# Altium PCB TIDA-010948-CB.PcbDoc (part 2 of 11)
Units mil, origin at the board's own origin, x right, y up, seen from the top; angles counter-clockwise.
Board outline 8100 x 8400 mil, 8 copper layers (L01 - TOP, L02 - GND, L03 - SIG, L04 - GND, L05 - PWR, L06 - SIG, L07 - GND, L08 - BOTTOM), stack 59.656 mil thick; 711 components, 572 nets, 2646 pads, 1325 vias.
Unrouted connection lines stored in the file: 988.
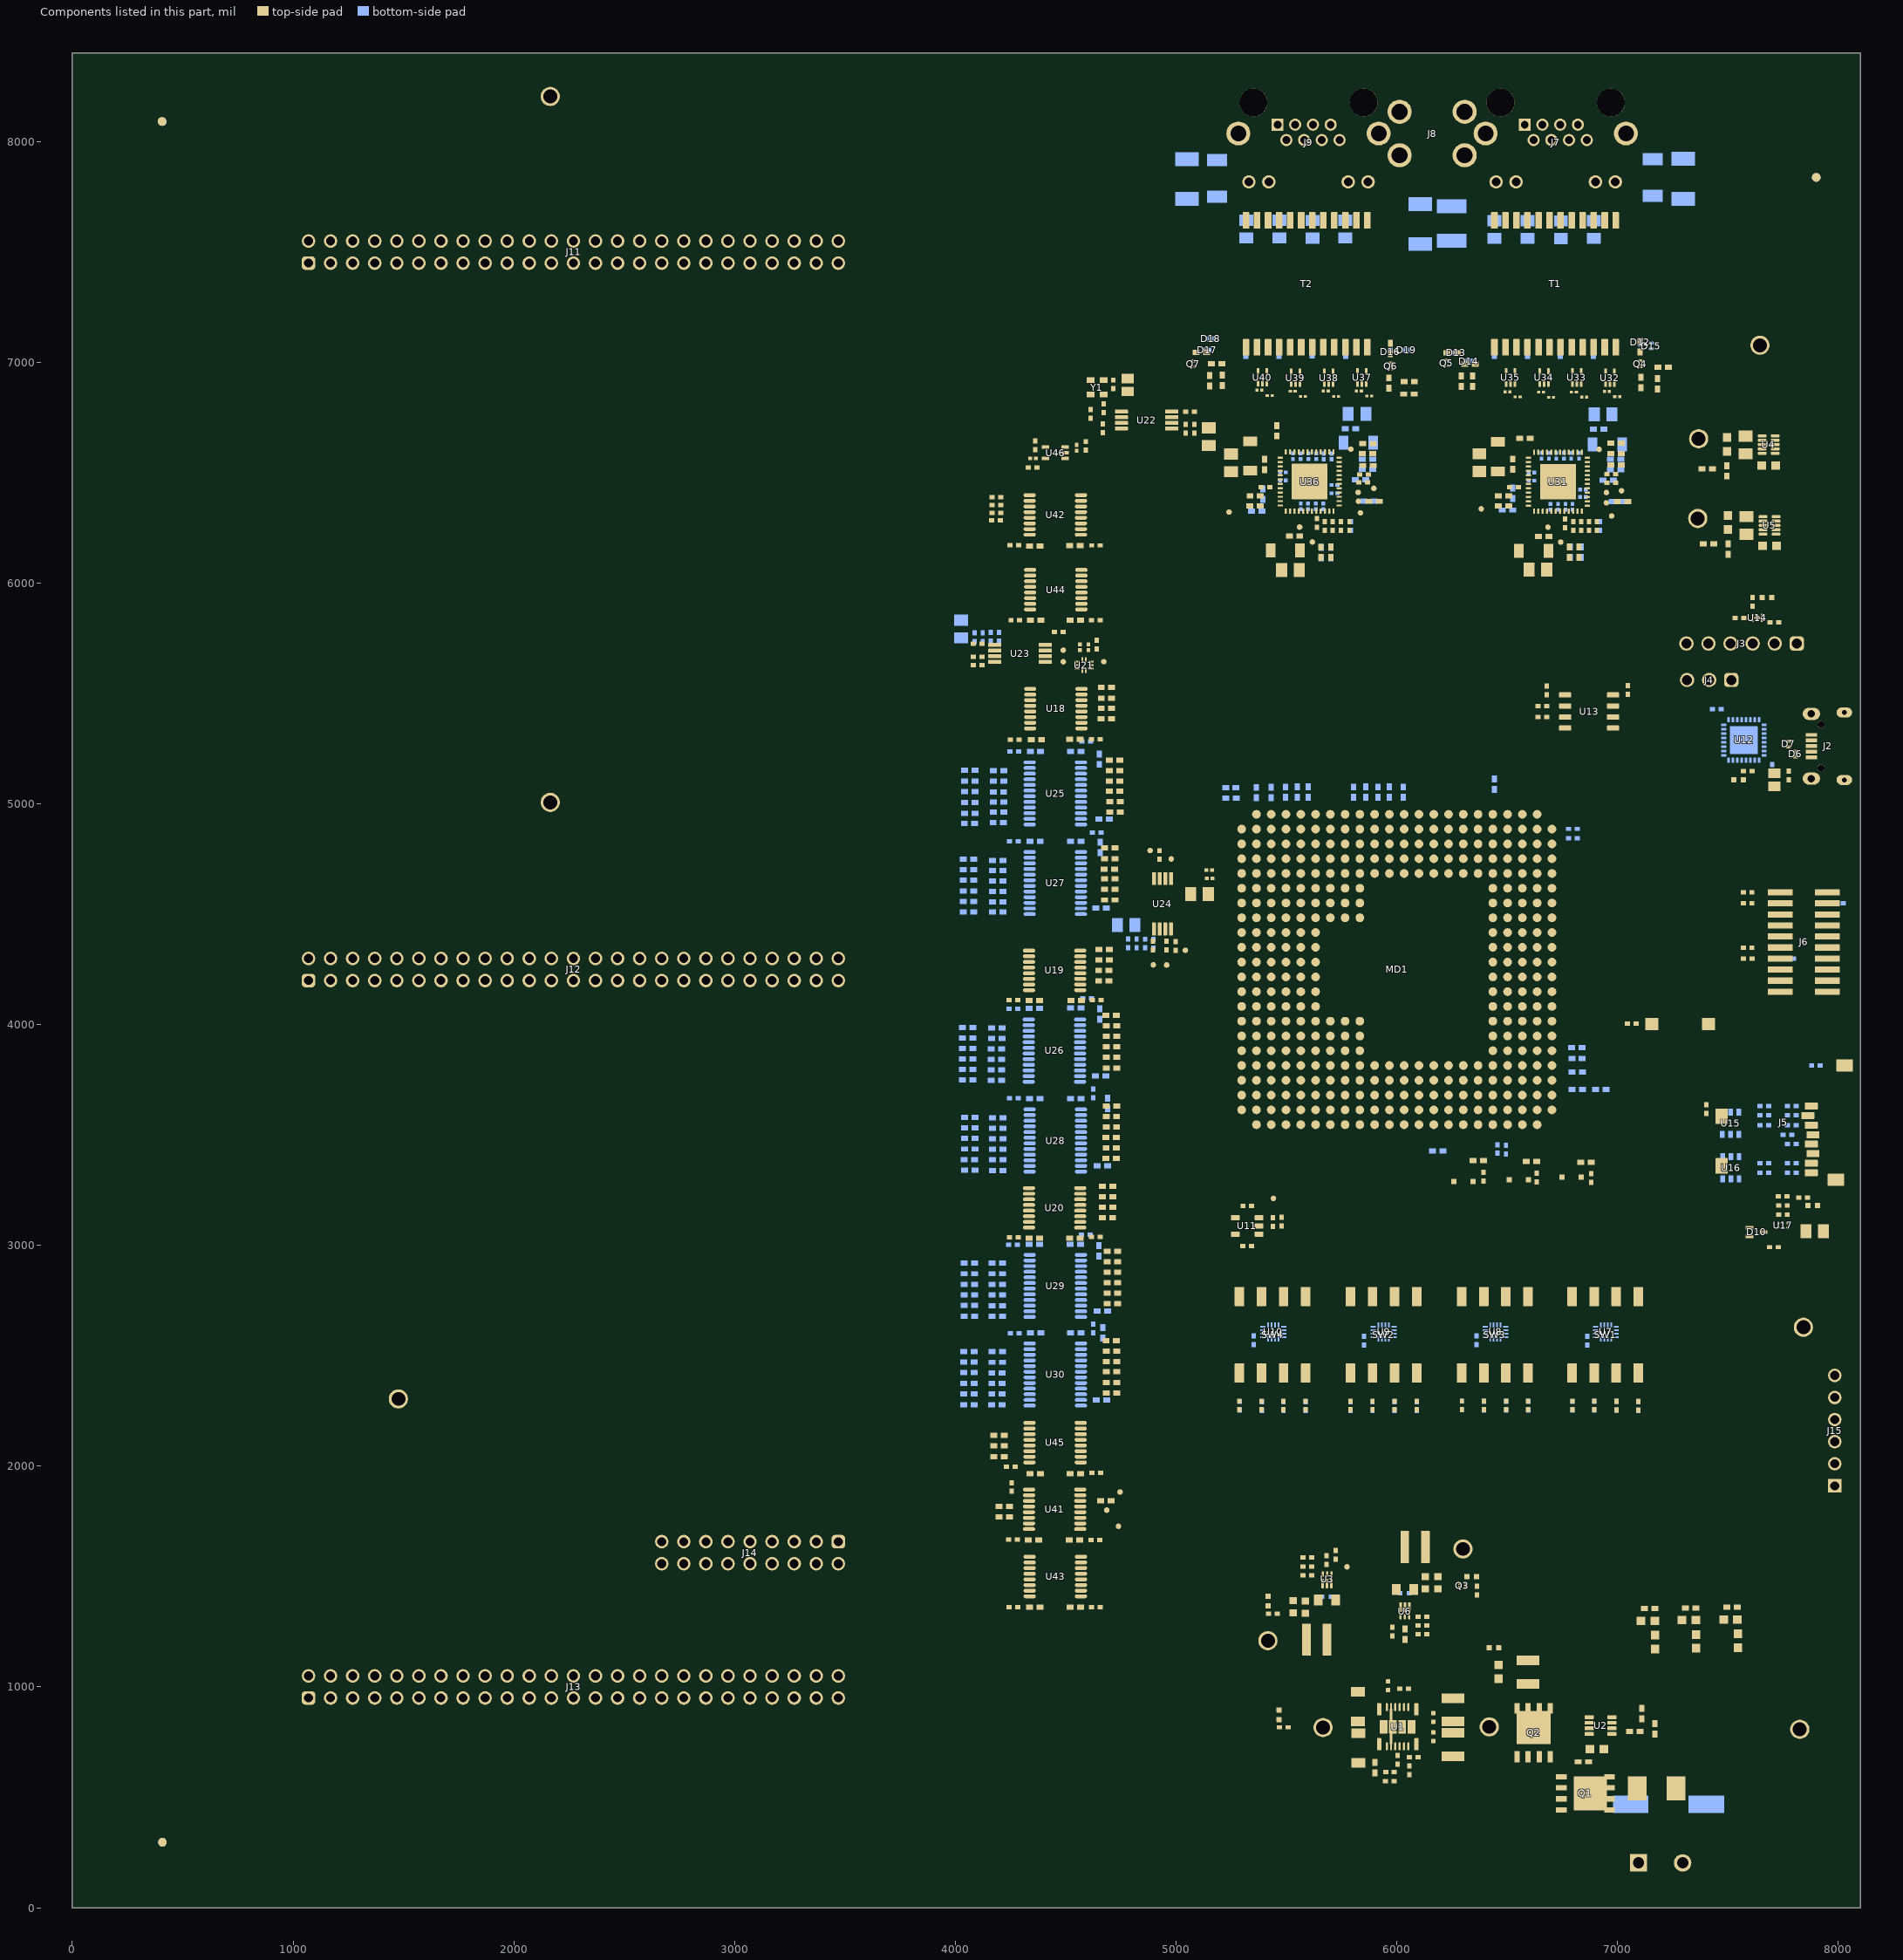
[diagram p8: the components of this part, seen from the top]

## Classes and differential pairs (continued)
net class Bootmode[0..15]: Bootmode0 Bootmode1 Bootmode2 Bootmode3 Bootmode4 Bootmode5 Bootmode6 Bootmode7 Bootmode8 Bootmode9 Bootmode10 Bootmode11 Bootmode12 Bootmode13 Bootmode14 Bootmode15
component class TIDA-010948-CB-Hardware: !PCB1 FID1 FID2 FID3 FID4 FID5 FID6 LBL1 Logo2 Logo3
component class Header: J3 J4 J6 J11 J12 J13 J14 J15
component class FiducialMark: FID1 FID2 FID3 FID4 FID5 FID6
component class Label: LBL1
differential pair ETH2_TD_D: +ETH2_TD_D_P -ETH2_TD_D_N
differential pair ETH2_TD_C: +ETH2_TD_C_P -ETH2_TD_C_N
differential pair ETH2_TD_B: +ETH2_TD_B_P -ETH2_TD_B_N
differential pair ETH2_TD_A: +ETH2_TD_A_P -ETH2_TD_A_N
differential pair ETH1_TD_D: +ETH1_TD_D_P -ETH1_TD_D_N
differential pair ETH1_TD_C: +ETH1_TD_C_P -ETH1_TD_C_N
differential pair ETH1_TD_B: +ETH1_TD_B_P -ETH1_TD_B_N
differential pair ETH1_TD_A: +ETH1_TD_A_P -ETH1_TD_A_N
differential pair E2_TD_D: +E2_TD_D_P -E2_TD_D_N
differential pair E2_TD_C: +E2_TD_C_P -E2_TD_C_N
differential pair E2_TD_B: +E2_TD_B_P -E2_TD_B_N
differential pair E2_TD_A: +E2_TD_A_P -E2_TD_A_N
differential pair E1_TD_D: +E1_TD_D_P -E1_TD_D_N
differential pair E1_TD_C: +E1_TD_C_P -E1_TD_C_N
differential pair E1_TD_B: +E1_TD_B_P -E1_TD_B_N
differential pair E1_TD_A: +E1_TD_A_P -E1_TD_A_N
differential pair FTDI_USB_D: +FTDI_USB_D_P -FTDI_USB_D_N

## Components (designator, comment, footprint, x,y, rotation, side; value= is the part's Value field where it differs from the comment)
C1 "GRM32ER71H106KA12L" 1210_270L 6255,896 r90 top locked value=10uF
C2 "GRM32ER71H106KA12L" 1210_270L 6255,739 r270 top locked value=10uF
C3 "EEE-FK1H221P" SM_RADIAL_G 7230.83,467.83 r0 bottom value=220uF
C4 "885012205086" FP-885012205086_0402-MFG 6165,774 r270 top locked value=100nF
C5 "885012205086" FP-885012205086_0402-MFG 6165,862 r90 top locked value=100nF
C6 "C3216X5R1E476M160AC" 1206_190 5825,723 r90 top locked value=47uF
C7 "C3216X5R1E476M160AC" 1206_190 5824.5,911 r270 top locked value=47uF
C8 "885012205086" FP-885012205086_0402-MFG 5961,1005 r270 top locked value=100nF
C9 "CGA2B2NP01H220J050BA" 0402L 5969,615 r0 top locked value=22pF
C10 "GRM32ER71H106KA12L" 1210_270L 6595,1067 r270 top locked value=10uF
C11 "GCM188R71H104KA57D" 0603 6906,719 r180 top locked value=0.1uF
C12 "885012205086" FP-885012205086_0402-MFG 5682,1409 r0 bottom value=100nF
C13 "C2012JB1V106K125AC" 0805_HV1 5684,1393 r180 top locked value=10uF
C14 "GRM1555C1H121JA01D" 0402L 5595,1586 r0 top value=120pF
C15 "GRM188Z71A106MA73D" 0603 7684.6,6532.26 r180 top locked value=10uF
C16 "GRM1885C1H121JA01D" 0603 7496.6,6627.26 r270 top locked value=120pF
C17 "GRM187R61A226ME15D" 0603L 5586,1362 r90 top locked value=22uF
C18 "GRM187R61A226ME15D" 0603L 5530.5,1362.5 r90 top locked value=22uF
C19 "GRM21BR61E226ME44L" 0805_HV 7580.6,6625.26 r270 top locked value=22uF
C20 "885012205086" FP-885012205086_0402-MFG 6036,1425 r180 bottom value=100nF
C21 "C2012JB1V106K125AC" 0805_HV1 6037,1441 r0 top locked value=10uF
C22 "GRM188Z71A106MA73D" 0603 7688.61,6169.05 r180 top locked value=10uF
C23 "GRM1885C1H131JA01D" 0603 7499.61,6274.05 r270 top locked value=130pF
C24 "GRM21BR61E226ME44L" 0805_HV 7584.61,6261.05 r270 top locked value=22uF
C25 "GRM1555C1H121JA01D" 0402L 6116.5,1238.5 r180 top value=120pF
C26 "GRM187R61A226ME15D" 0603L 6129,1472 r270 top locked value=22uF
C27 "GRM187R61A226ME15D" 0603L 6186,1471.5 r270 top value=22uF
C28 "885012105016" 0402L 5322,2996 r0 top value=0.1uF
C29 "GRM155R61E105MA12D" 0402L 5438,3106 r90 top value=1uF
C30 "885012105016" 0402L 6862,2568 r270 bottom value=0.1uF
C31 "885012105016" 0402L 6362,2571 r270 bottom value=0.1uF
C32 "885012105016" 0402L 5852,2568 r270 bottom value=0.1uF
C33 "885012105016" 0402L 5352,2570 r270 bottom value=0.1uF
C34 "885012105016" 0402L 7047,5516 r90 top value=0.1uF
C35 "885012105016" 0402L 6680,5514 r90 top value=0.1uF
C36 "885012105016" 0402L 7449,5429 r180 bottom value=0.1uF
C37 "885012105016" 0402L 7776,5128 r270 top value=0.1uF
C38 "885012207026" 0805L 7710,5108 r270 top value=10uF
C39 "GRM155R61E105MA12D" 0402L 7553,5842 r180 top value=1uF
C40 "GRM155R61E105MA12D" 0402L 7711,5822 r0 top value=1uF
C41 "GCM155R71C224KE02D" 0402 6857,3377 r0 top value=0.22uF
C42 "GCM155R71C224KE02D" 0402 6610,3381 r0 top value=0.22uF
C43 "GCM155R71C224KE02D" 0402 6368.5,3385 r0 top value=0.22uF
C44 "885012105012" 0402L 7749,3140 r180 top value=1uF
C45 "885012105016" 0402L 7770,3501 r180 bottom value=0.1uF
C46 "885012207026" 0805_HV 7893,3064 r0 top value=10uF
C47 "GRM155R71A104KA01D" 0402 4542.5,5291.5 r0 top value=0.1uF
C48 "GRM155R71A104KA01D" 0402 4367,5290 r0 top value=0.1uF
C49 "GRM155R71A104KA01D" 0402 4547.1,4109.65 r0 top value=0.1uF
C50 "GRM155R71A104KA01D" 0402 4357.5,4109 r0 top value=0.1uF
C51 "GRM155R71A104KA01D" 0402 4541.45,3033 r0 top value=0.1uF
C52 "GRM155R71A104KA01D" 0402 4358.5,3032.5 r0 top value=0.1uF
C53 "885012105012" 0402L 5083,6698.5 r270 top locked value=1uF
C54 "885012105016" 0402L 5043,6699 r270 top value=0.1uF
C55 "GRM033Z71C104KE14D" 0201 4564.5,5709 r90 top value=0.1uF
C56 "GRM033Z71C104KE14D" 0201 4603,5709 r270 top value=0.1uF
C57 "885012105016" 0402L 4715.5,6899.5 r270 top locked value=0.1uF
C58 "885012207092" 0805L 4780.05,6897.37 r270 top locked value=0.01uF
C59 "885012105012" 0402L 4198,5756.5 r90 bottom value=1uF
C60 "885012105016" 0402L 4086.5,5755.5 r90 bottom value=0.1uF
C61 "885012105016" 0402L 4123.93,5755.04 r90 bottom value=0.1uF
C62 "885012105016" 0402L 4159.77,5756.15 r90 bottom value=0.1uF
C63 "885012105016" 0402L 4897.69,4366.88 r270 bottom value=0.1uF
C64 "885012105012" 0402L 4782.27,4367.34 r270 bottom value=1uF
C65 "885012105016" 0402L 4821.26,4367.34 r270 bottom value=0.1uF
C66 "885012105012" 0402L 4859.62,4367.03 r270 bottom value=1uF
C67 "0402YC101KAT2A" 0402 4064.58,4911.19 r180 bottom value=100pF
C68 "0402YC101KAT2A" 0402 4064.89,4957.08 r180 bottom value=100pF
C69 "0402YC101KAT2A" 0402 4065.04,5006.33 r180 bottom value=100pF
C70 "0402YC101KAT2A" 0402 4065.5,5054.5 r180 bottom value=100pF
C71 "0402YC101KAT2A" 0402 4064.99,5102.82 r180 bottom value=100pF
C72 "0402YC101KAT2A" 0402 4064.99,5151.32 r180 bottom value=100pF
C73 "0402YC101KAT2A" 0402 4056,3749.5 r180 bottom value=100pF
C74 "0402YC101KAT2A" 0402 4056,3797.5 r180 bottom value=100pF
C75 "0402YC101KAT2A" 0402 4056,3845 r180 bottom value=100pF
C76 "0402YC101KAT2A" 0402 4056.31,3892.63 r180 bottom value=100pF
C77 "0402YC101KAT2A" 0402 4055.97,3939.21 r180 bottom value=100pF
C78 "0402YC101KAT2A" 0402 4056.23,3986.96 r180 bottom value=100pF
C79 "GRM155R71A104KA01D" 0402 4546.5,5238 r0 bottom value=0.1uF
C80 "GRM155R71A104KA01D" 0402 4546.5,4075 r0 bottom value=0.1uF
C81 "0402YC101KAT2A" 0402 4060.5,4510 r180 bottom value=100pF
C82 "0402YC101KAT2A" 0402 4060,4557 r180 bottom value=100pF
C83 "0402YC101KAT2A" 0402 4059.5,4605 r180 bottom value=100pF
C84 "0402YC101KAT2A" 0402 4059.5,4653.5 r180 bottom value=100pF
C85 "0402YC101KAT2A" 0402 4059.5,4701 r180 bottom value=100pF
C86 "0402YC101KAT2A" 0402 4059.5,4748.5 r180 bottom value=100pF
C87 "0402YC101KAT2A" 0402 4065,3340.5 r180 bottom value=100pF
C88 "0402YC101KAT2A" 0402 4064.5,3388.5 r180 bottom value=100pF
C89 "0402YC101KAT2A" 0402 4065,3436.5 r180 bottom value=100pF
C90 "0402YC101KAT2A" 0402 4065,3484 r180 bottom value=100pF
C91 "0402YC101KAT2A" 0402 4065,3531.5 r180 bottom value=100pF
C92 "0402YC101KAT2A" 0402 4065.29,3579.09 r180 bottom value=100pF
C93 "GRM155R71A104KA01D" 0402 4546.15,4830.19 r0 bottom value=0.1uF
C94 "GRM155R71A104KA01D" 0402 4545,3665.5 r0 bottom value=0.1uF
C95 "0402YC101KAT2A" 0402 4064.5,2679.5 r180 bottom value=100pF
C96 "0402YC101KAT2A" 0402 4064.5,2727.5 r180 bottom value=100pF
C97 "0402YC101KAT2A" 0402 4064,2776 r180 bottom value=100pF
C98 "0402YC101KAT2A" 0402 4064,2824 r180 bottom value=100pF
C99 "0402YC101KAT2A" 0402 4064,2871.5 r180 bottom value=100pF
C100 "0402YC101KAT2A" 0402 4064,2919.5 r180 bottom value=100pF
C101 "GRM155R71A104KA01D" 0402 4543.68,3005.21 r0 bottom value=0.1uF
C102 "0402YC101KAT2A" 0402 4061.16,2278.07 r180 bottom value=100pF
C103 "0402YC101KAT2A" 0402 4061.39,2326.39 r180 bottom value=100pF
C104 "0402YC101KAT2A" 0402 4061.18,2374.62 r180 bottom value=100pF
C105 "0402YC101KAT2A" 0402 4061.32,2423.65 r180 bottom value=100pF
C106 "0402YC101KAT2A" 0402 4061.5,2471.1 r180 bottom value=100pF
C107 "0402YC101KAT2A" 0402 4061.5,2518.5 r180 bottom value=100pF
C108 "GRM155R71A104KA01D" 0402 4546.08,2603.11 r0 bottom value=0.1uF
C109 "C3216X7R1V106M160AC" 1206_190 6457.5,6573 r90 top locked value=10uF
C110 "GRM033C71C104KE14D" 0201_033 6609.5,6500.5 r0 bottom value=0.1uF
C111 "GRM033C71C104KE14D" 0201_033 6730,6345 r90 bottom value=0.1uF
C112 "GRM155R71A104KA01D" 0402 4363,5237 r0 bottom value=0.1uF
C113 "C3216X7R1V106M160AC" 1206_190 6953.89,6628.35 r0 bottom value=10uF
C114 "GRM033C71C104KE14D" 0201_033 6790,6576.52 r270 bottom value=0.1uF
C115 "GRM033C71C104KE14D" 0201_033 6689.61,6576.62 r270 bottom value=0.1uF
C116 "C3216X7R1V106M160AC" 1206_190 6619.5,6146 r180 top locked value=10uF
C117 "GRM033C71C104KE14D" 0201_033 6764,6345 r90 bottom value=0.1uF
C118 "GRM033C71C104KE14D" 0201_033 6722.5,6577 r270 bottom value=0.1uF
C119 "GRM033C71C104KE14D" 0201_033 6843,6389.5 r180 bottom value=0.1uF
C120 "GRM155R71A104KA01D" 0402 4358,4073 r0 bottom value=0.1uF
C121 "885012205031" 0402 6525.5,6538 r90 top locked value=0.01uF
C122 "885012205031" 0402 6914.79,6696.09 r0 bottom value=0.01uF
C123 "885012205031" 0402 6666,6211.5 r180 top locked value=0.01uF
C124 "GRM033R61A105ME15D" 0201 6609.5,6463.5 r0 bottom value=1uF
C125 "GRM033R61A105ME15D" 0201 6696,6345 r90 bottom value=1uF
C126 "GRM155R71A104KA01D" 0402 4361.05,4829.5 r0 bottom value=0.1uF
C127 "GRM033R61A105ME15D" 0201 6824.76,6576.62 r270 bottom value=1uF
C128 "GRM033R61A105ME15D" 0201 6655.3,6576.75 r270 bottom value=1uF
C129 "GRM033R61A105ME15D" 0201 6796,6345 r90 bottom value=1uF
C130 "GRM033R61A105ME15D" 0201 6757.5,6577 r270 bottom value=1uF
C131 "GRM033R61A105ME15D" 0201 6843,6423.5 r180 bottom value=1uF
C132 "GRM155R71A104KA01D" 0402 4360.52,3665.11 r0 bottom value=0.1uF
C133 "GRM155R71C104KA88D" 0402 6441.5,7054.5 r270 bottom value=0.1uF
C134 "GRM155R71C104KA88D" 0402 6592,7054 r270 bottom value=0.1uF
C135 "C1005X7R1C103K050BA" 0402 6923.5,3706.5 r0 bottom value=0.01uF
C136 "885012105010" 0402 6331,6991.5 r0 top value=0.1uF
C137 "GRM155R71C104KA88D" 0402 6741,7055 r270 bottom value=0.1uF
C138 "CGA2B2NP01H220J050BA" 0402L 6530.5,6433.5 r180 top locked value=22pF
C139 "885012105010" 0402 7207,6977.5 r180 top value=0.1uF
C140 "GRM155R71C104KA88D" 0402 6891.5,7053.5 r270 bottom value=0.1uF
C141 "GR442QR73D102KW01L" 1808 7159,7837 r90 bottom value=1000pF
C142 "GRM0335C1H4R7CA01D" 0201L 6998.5,6844 r180 top value=4.7pF
C143 "GRM0335C1H4R7CA01D" 0201L 6952,6868 r0 top value=4.7pF
C144 "GRM0335C1H4R7CA01D" 0201L 6849,6842 r180 top value=4.7pF
C145 "GRM0335C1H4R7CA01D" 0201L 6802.5,6865.5 r0 top value=4.7pF
C146 "GRM0335C1H4R7CA01D" 0201L 6699.5,6841.5 r180 top value=4.7pF
C147 "GRM0335C1H4R7CA01D" 0201L 6653,6865 r0 top value=4.7pF
C148 "GRM0335C1H4R7CA01D" 0201L 6547.5,6843 r180 top value=4.7pF
C149 "GRM0335C1H4R7CA01D" 0201L 6501,6866 r0 top value=4.7pF
C150 "1812SC103KAT1A" 1812 6249,7628.5 r270 bottom value=0.01uF
C151 "C3216X7R1V106M160AC" 1206_190 5335.5,6575.5 r90 top locked value=10uF
C152 "GRM033C71C104KE14D" 0201_033 5484.5,6465 r0 bottom value=0.1uF
C153 "GRM033C71C104KE14D" 0201_033 5598,6347 r90 bottom value=0.1uF
C154 "GRM155R71A104KA01D" 0402 4357.68,3005.08 r0 bottom value=0.1uF
C155 "C3216X7R1V106M160AC" 1206_190 5825.95,6635.6 r0 bottom value=10uF
C156 "GRM033C71C104KE14D" 0201_033 5704,6573.5 r270 bottom value=0.1uF
C157 "GRM033C71C104KE14D" 0201_033 5529,6574 r270 bottom value=0.1uF
C158 "C3216X7R1V106M160AC" 1206_190 5495,6147 r180 top locked value=10uF
C159 "GRM033C71C104KE14D" 0201_033 5633,6347 r90 bottom value=0.1uF
C160 "GRM033C71C104KE14D" 0201_033 5718,6407 r180 bottom value=0.1uF
C161 "GRM033C71C104KE14D" 0201_033 5635,6574 r270 bottom value=0.1uF
C162 "GRM155R71A104KA01D" 0402 4363.5,2603 r0 bottom value=0.1uF
C163 "885012205031" 0402 5401,6537.5 r90 top locked value=0.01uF
C164 "885012205031" 0402 5790.5,6699 r0 bottom value=0.01uF
C165 "885012205031" 0402 5536.5,6213.5 r180 top locked value=0.01uF
C166 "GRM033R61A105ME15D" 0201 5484.5,6501.5 r0 bottom value=1uF
C167 "GRM033R61A105ME15D" 0201 5565.5,6347 r90 bottom value=1uF
C168 "GRM033R61A105ME15D" 0201 5151.96,4662.54 r180 top value=1uF
C169 "GRM033R61A105ME15D" 0201 5669,6573.5 r270 bottom value=1uF
C170 "GRM033R61A105ME15D" 0201 5564,6574 r270 bottom value=1uF
C171 "GRM033R61A105ME15D" 0201 5666.5,6347 r90 bottom value=1uF
C172 "GRM033R61A105ME15D" 0201 5718,6444.5 r180 bottom value=1uF
C173 "GRM033R61A105ME15D" 0201 5599.5,6574 r270 bottom value=1uF
C174 "GRM033C71C104KE14D" 0201_033 5150.5,4700 r180 top value=0.1uF
C175 "GRM155R71C104KA88D" 0402 5317,7055 r270 bottom value=0.1uF
C176 "GRM155R71C104KA88D" 0402 5467,7055 r270 bottom value=0.1uF
C177 "GRM155R71A104KA01D" 0402 7144.86,1355.4 r0 top locked value=0.1uF
C178 "885012105010" 0402 5183.5,6994 r0 top locked value=0.1uF
C179 "GRM155R71C104KA88D" 0402 5617,7057 r270 bottom value=0.1uF
C180 "CGA2B2NP01H220J050BA" 0402L 5405.5,6433.5 r180 top locked value=22pF
C181 "885012105010" 0402 6056,6912.5 r180 top locked value=0.1uF
C182 "GRM155R71C104KA88D" 0402 5768,7055 r270 bottom value=0.1uF
C183 "GR442QR73D102KW01L" 1808 5186,7833 r90 bottom value=1000pF
C184 "GRM0335C1H4R7CA01D" 0201L 5875,6846.5 r180 top locked value=4.7pF
C185 "GRM0335C1H4R7CA01D" 0201L 5828.5,6870 r0 top locked value=4.7pF
C186 "GRM0335C1H4R7CA01D" 0201L 5725,6845.5 r180 top locked value=4.7pF
C187 "GRM0335C1H4R7CA01D" 0201L 5678.5,6869.5 r0 top locked value=4.7pF
C188 "GRM0335C1H4R7CA01D" 0201L 5574.5,6845 r180 top locked value=4.7pF
C189 "GRM0335C1H4R7CA01D" 0201L 5528.5,6869 r0 top locked value=4.7pF
C190 "GRM0335C1H4R7CA01D" 0201L 5424,6849 r180 top locked value=4.7pF
C191 "GRM0335C1H4R7CA01D" 0201L 5377.5,6873.5 r0 top locked value=4.7pF
C193 "GRM155R71A104KA01D" 0402 4540.5,1665.5 r0 top value=0.1uF
C194 "GRM155R71A104KA01D" 0402 4354.44,1665.64 r0 top value=0.1uF
C195 "GRM155R71A104KA01D" 0402 4542,6170 r0 top value=0.1uF
C196 "GRM155R71A104KA01D" 0402 4360,6167 r0 top value=0.1uF
C197 "GRM155R71A104KA01D" 0402 4543.5,1362 r0 top value=0.1uF
C198 "GRM155R71A104KA01D" 0402 4359.81,1361.62 r0 top value=0.1uF
C199 "GRM155R71A104KA01D" 0402 4544.5,5831.5 r0 top value=0.1uF
C200 "GRM155R71A104KA01D" 0402 4364.79,5831.71 r0 top value=0.1uF
C201 "GRM155R71A104KA01D" 0402 4543,1966 r0 top value=0.1uF
C202 "GRM155R71A104KA01D" 0402 4362.8,1966.16 r0 top value=0.1uF
C203 "GRM033Z71C104KE14D" 0201 4351.5,6564.5 r180 top value=0.1uF
C204 "GRM033Z71C104KE14D" 0201 4549.5,6613 r90 top locked value=0.1uF
C205 "GRM155R71A104KA01D" 0402 7330.5,1357 r0 top locked value=0.1uF
C206 "GRM155R71A104KA01D" 0402 7518.38,1362.05 r0 top locked value=0.1uF
D1 "150040GS73240" WL-SMCC_0402_Green 6440,1177 r0 top locked value=Green
D2 "150040GS73240" WL-SMCC_0402_Green 5466.69,874 r270 top locked value=Green
D3 "SMBJ33CA-13-F" SMB-Bi 7177,541 r180 top locked value=33V
D4 "150040GS73240" WL-SMCC_0402_Green 5417,1389 r270 top locked value=Green
D5 "150040GS73240" WL-SMCC_0402_Green 6339.5,1500 r0 top locked value=Green
D6 "ESD321DPYR" DPY0002A#1 7806,5225.5 r270 top
D7 "ESD321DPYR" DPY0002A#1 7774,5271 r90 top
D8 "150040GS73240" WL-SMCC_0402_Green 7547.61,5109.2 r0 top value=Green
D9 "150040GS73240" WL-SMCC_0402_Green 7677,5935 r180 top value=Green
D10 "BAT54AT-7-F" SOT-523 7630,3061 r0 top value=30V
D11 "150040GS73240" WL-SMCC_0402_Green 7884.48,3180.4 r180 top value=Green
D12 "TPD1E1B04DPYR" DPY0002A#2 7102.5,7090.5 r90 bottom
D13 "TPD1E1B04DPYR" DPY0002A#2 6269,7043 r0 bottom
D14 "TPD1E1B04DPYR" DPY0002A#2 6327,7005 r0 bottom
D15 "TPD1E1B04DPYR" DPY0002A#2 7153,7073.7 r90 bottom
D16 "TPD1E1B04DPYR" DPY0002A#2 5970.5,7047 r90 bottom
D17 "TPD1E1B04DPYR" DPY0002A#2 5140.5,7055.5 r0 bottom
D18 "TPD1E1B04DPYR" DPY0002A#2 5156.43,7106.61 r0 bottom
D19 "TPD1E1B04DPYR" DPY0002A#2 6045,7055 r180 bottom
D20 "BAT54WSQ-7-F" SOD-323 6302.5,3289.5 r0 top value=30V
D21 "BAT54WSQ-7-F" SOD-323 6553.5,3298 r0 top value=30V
D22 "BAT54WSQ-7-F" SOD-323 6792,3308.5 r0 top value=30V
FID1 "Fiducial" Fiducial10-20 406,8091 r90 top
FID2 "Fiducial" Fiducial10-20 408,8090 r90 bottom
FID3 "Fiducial" Fiducial10-20 408,296.5 r90 top
FID4 "Fiducial" Fiducial10-20 408,296.5 r90 bottom
FID5 "Fiducial" Fiducial10-20 7900,7837.5 r90 top
FID6 "Fiducial" Fiducial10-20 7900,7837.5 r90 bottom
J1 "1711725" FP-1888687_HDR2-MFG 7195,203 r0 top locked
J2 "629105150521" FP-629105150521_CONN_USB_8MM0_6MM6-MFG 7878,5261 r90 top locked
J3 "61300611121" WURTH_61300611121 7562,5726 r180 top locked
J4 "61300311121" WURTH_61300311121 7415,5561 r180 top locked
J5 "693071010811" Molex_693071010811 7755.38,3555.08 r270 top
J6 "FTR-110-51-S-D-06" Samtec_FTR-110-51-x-D-06 7844,4374 r0 top locked
J7 "615108137421R" FP-615108137421R_CONN_JACK_16MM4_15MM7-MFG 6720,8080 r180 top locked
J8 "7781" Keystone_7781 6160,8036 r90 top locked
J9 "615108137421R" FP-615108137421R_CONN_JACK_16MM4_15MM7-MFG 5600,8080 r180 top locked
J11 "TSW-125-08-L-D" Samtec_TSW-125-08-x-D 2270,7499.2 r90 top
J12 "TSW-125-08-L-D" Samtec_TSW-125-08-x-D 2270,4249.6 r90 top locked
J13 "TSW-125-08-L-D" Samtec_TSW-125-08-x-D 2270,1000 r90 top
J14 "TSW-109-09-L-D" Samtec_TSW-109-09-x-D 3070,1608 r270 top
J15 "PBC06SAAN" Sullins_PxC06SAAN 7984,2161 r90 top
L1 "744383560047HT" FP-744383560047HT_1616-MFG 5637,1214 r180 top value=0.47uH
L2 "744383560047HT" FP-744383560047HT_1616-MFG 6083,1634 r0 top value=0.47uH
L3 "742792062" 0805_HV 5148,6663 r270 top locked value="80 ohm"
L4 "742792062" 0805_HV 4026,5792 r90 bottom value="80 ohm"
L5 "742792062" 0805_HV 4774,4450.5 r180 bottom value="80 ohm"
L6 "742792062" 0805_HV 6374,6545.5 r90 top locked value="80 ohm"
L7 "742792062" 0805_HV 6934.79,6763.59 r0 bottom value="80 ohm"
L8 "742792062" 0805_HV 6639,6060.5 r180 top locked value="80 ohm"
L9 "742792062" 0805_HV 5249,6544.5 r90 top locked value="80 ohm"
L10 "742792062" 0805_HV 5820,6766 r0 bottom value="80 ohm"
L11 "742792062" 0805_HV 5518,6059 r180 top locked value="80 ohm"
L12 "742792062" 0805_HV 5106.5,4590.5 r180 top value="80 ohm"
LBL1 "THT-14-423-10" Label_650x200 6093,4254 r90 top
Logo2 "FCC disclaimer" FCC_disclaimer 12152,9030 r0 top
Logo3 "WEEE logo" WEEE_Minimum 302.5,7418.5 r90 top
MD1 "TQMa2434L-AA" FP-TQMa2434L-AA_LGA366-MFG 6000,4249.6 r0 top locked
NT1 "Net-Tie" Net-Tie_10milWide_30milLong 5974,770 r90 top locked net-tie
NT2 "Net-Tie" Net-Tie_10milWide_30milLong 5974,871 r270 top locked net-tie
NT4 "Net-Tie" NetTie_0402 4672,6792.5 r270 top locked net-tie
Q1 "SI7892BDP" PowerPAK_SO-8 6854.5,518 r0 top locked value=30V
Q2 "SI7892BDP" PowerPAK_SO-8 6620,793 r90 top locked value=30V
Q3 "CSD13383F4" YJC0003A 6297,1459.84 r0 top locked value=12V
Q4 "MOSFET_N_D3G1S2_PD2" YJC0003A 7102.5,6992.5 r90 top value=12V
Q5 "MOSFET_N_D3G1S2_PD2" YJC0003A 6225.5,6996.5 r90 top locked value=12V
Q6 "MOSFET_N_D3G1S2_PD2" YJC0003A 5972.5,6982.5 r90 top locked value=12V
Q7 "MOSFET_N_D3G1S2_PD2" YJC0003A 5078,6993 r90 top locked value=12V
R1 "CRCW060368K0JNEA" 0603 6461,1068 r270 top locked value=68k
R2 "CRCW0402402KFKED" 0402L 6076,682 r180 top locked value=402k
R3 "CRCW040240K2FKED" 0402 5901,634 r90 top locked value=40.2k
R4 "CRCW0402133KFKED" 0402L 6056,622 r270 top locked value=133k
R5 "CRCW04020000Z0ED" 0402L 6034,992 r180 top locked value=0
R6 "CRCW040210K0FKED" 0402L 5968.5,573 r180 top value=10.0k
R7 "CRCW04028K20JNED" 0402L 5487.69,817 r0 top locked value=8.2k
R8 "CRCW040213K0FKED" 0402L 6004,669 r90 top locked value=13.0k
R9 "CRCW040210K0JNED" 0402 6845,661 r0 top locked value=10k
R10 "CRCW04020000Z0ED" 0402 7078,798 r180 top locked value=0
R11 "CRCW0402100KFKED" 0402 7170,810 r270 top locked value=100k
R12 "CRCW04024K30JNED" 0402 7109,879 r270 top locked value=4.3k
R13 "CRCW040210K0FKED" 0402L 5682,1574 r90 top locked value=10.0k
R14 "CRCW04023K30JNED" 0402L 5438,1331 r0 top locked value=3.3k
R15 "CRCW0402316KFKED" 0402 7406.6,6517.26 r180 top locked value=316k
R16 "CRCW0402453KFKED" 0402L 5595,1545.5 r180 top locked value=453k
R17 "CRCW0402100KFKED" 0402L 5595,1506 r0 top locked value=100k
R18 "CRCW0402100KFKED" 0402 7495.6,6508.26 r90 top locked value=100k
R19 "CRCW040210K0FKED" 0402L 5723,1598 r270 top value=10.0k
R20 "CRCW040273K2FKED" 0402 7412.61,6178.05 r180 top locked value=73.2k
R21 "CRCW04023K30JNED" 0402L 6363,1436.84 r270 top locked value=3.3k
R22 "CRCW040249K9FKED" 0402 6037,1238 r270 top locked value=49.9k
R23 "CRCW040288K7FKED" 0402 7501.61,6153.05 r90 top locked value=88.7k
R24 "CRCW0402200KFKED" 0402L 6116,1277.5 r0 top locked value=200k
R25 "CRCW0402100KFKED" 0402L 6116,1318 r180 top locked value=100k
R26 "CRCW040210K0FKED" 0402L 5979,1250 r90 top locked value=10.0k
R27 "CRCW04021K00FKED" 0402L 6795,2273 r90 bottom value=1.00k
R28 "CRCW04021K00FKED" 0402L 5790,2272 r90 bottom value=1.00k
R29 "CRCW04021K00FKED" 0402L 6895,2274 r90 bottom value=1.00k
R30 "CRCW04021K00FKED" 0402L 5890,2272 r90 bottom value=1.00k
R31 "CRCW04021K00FKED" 0402L 6995,2274 r90 bottom value=1.00k
R32 "CRCW04021K00FKED" 0402L 5990,2272 r90 bottom value=1.00k
R33 "CRCW04021K00FKED" 0402L 7095,2272 r90 bottom value=1.00k
R34 "CRCW04021K00FKED" 0402L 6091,2271 r90 bottom value=1.00k
R35 "CRCW040210K0FKED" 0402L 7094,2274 r90 top value=10.0k
R36 "CRCW040210K0FKED" 0402L 6995,2274 r90 top value=10.0k
R37 "CRCW040210K0FKED" 0402L 6895,2275 r90 top value=10.0k
R38 "CRCW040210K0FKED" 0402L 6795,2275 r90 top value=10.0k
R39 "CRCW040210K0FKED" 0402L 6090,2275 r90 top value=10.0k
R40 "CRCW040210K0FKED" 0402L 5990,2275 r90 top value=10.0k
R41 "CRCW040210K0FKED" 0402L 5890,2275 r90 top value=10.0k
R42 "CRCW040210K0FKED" 0402L 5790,2275 r90 top value=10.0k
R43 "CRCW04021K00FKED" 0402L 6295,2275 r90 bottom value=1.00k
R44 "CRCW04021K00FKED" 0402L 5288,2273 r90 bottom value=1.00k
R45 "CRCW04021K00FKED" 0402L 6395,2274 r90 bottom value=1.00k
R46 "CRCW04021K00FKED" 0402L 5389,2272 r90 bottom value=1.00k
R47 "CRCW04021K00FKED" 0402L 6495,2274 r90 bottom value=1.00k
R48 "CRCW04021K00FKED" 0402L 5487,2272 r90 bottom value=1.00k
R49 "CRCW04021K00FKED" 0402L 6596,2274 r90 bottom value=1.00k
R50 "CRCW04021K00FKED" 0402L 5587,2272 r90 bottom value=1.00k
R51 "CRCW040210K0FKED" 0402L 6595,2275 r90 top value=10.0k
R52 "CRCW040210K0FKED" 0402L 6495,2275 r90 top value=10.0k
R53 "CRCW040210K0FKED" 0402L 6395,2275 r90 top value=10.0k
R54 "CRCW040210K0FKED" 0402L 6295,2275 r90 top value=10.0k
R55 "CRCW040210K0FKED" 0402L 5587,2275 r90 top value=10.0k
R56 "CRCW040210K0FKED" 0402L 5486,2275 r90 top value=10.0k
R57 "CRCW040210K0FKED" 0402L 5387,2275 r90 top value=10.0k
R58 "CRCW040210K0FKED" 0402L 5287,2275 r90 top value=10.0k
R59 "CRCW040210K0FKED" 0402L 5479,3107 r270 top value=10.0k
R60 "CRCW040210K0FKED" 0402L 5323,3179 r180 top value=10.0k
R61 "ERJ-2GE0R00X" 0402L 6660,5443 r0 top value=0
R62 "CRCW040210K0FKED" 0402L 7701,5158 r270 bottom value=10.0k
R63 "ERJ-2GE0R00X" 0402L 6660,5393 r0 top value=0
R64 "CRCW04028K20JNED" 0402L 7590,5149 r0 top value=8.2k
R65 "CRCW040222R0JNED" 0402 6816.5,3846.5 r180 bottom value=22
R66 "CRCW040222R0JNED" 0402 6815.5,3895.5 r180 bottom value=22
R67 "CRCW04028K20JNED" 0402L 7612,5915 r270 top value=8.2k
R68 "CRCW040210K0FKED" 0402L 7665,3632 r180 bottom value=10.0k
R69 "CRCW040210K0FKED" 0402L 7665,3590 r180 bottom value=10.0k
R70 "CRCW040210K0FKED" 0402L 7665,3545 r180 bottom value=10.0k
R71 "CRCW040210K0FKED" 0402L 7665,3372 r180 bottom value=10.0k
R72 "CRCW040210K0FKED" 0402L 7665,3328 r180 bottom value=10.0k
R73 "CRCW04021K00FKED" 0402L 6392,3310.5 r90 top value=1.00k
R74 "ERJ-2GE0R00X" 0402L 7789,3632 r0 bottom value=0
R75 "CRCW04021K00FKED" 0402L 6633.63,3307.31 r90 top value=1.00k
R76 "ERJ-2GE0R00X" 0402L 7789,3590 r0 bottom value=0
R77 "CRCW04021K00FKED" 0402L 6881,3304.5 r90 top value=1.00k
R78 "ERJ-2GE0R00X" 0402L 7789,3545 r0 bottom value=0
R79 "ERJ-2GE0R00X" 0402L 7790,3459 r0 bottom value=0
R80 "ERJ-2GE0R00X" 0402L 7789,3372 r0 bottom value=0
R81 "ERJ-2GE0R00X" 0402L 7789,3328 r0 bottom value=0
R82 "CRCW0402200RFKED" 0402L 7402.83,3616.83 r90 top value=200
R83 "CRCW040210K0FKED" 0402L 7899,3814 r0 bottom value=10.0k
R84 "ERJ-2GE0R00X" 0402L 8002,4550 r180 bottom value=0
R85 "ERJ-2GE0R00X" 0402L 7065,4003.5 r180 top value=0
R86 "CRCW040210K0FKED" 0402L 7590,4299 r180 top value=10.0k
R87 "CRCW040210K0FKED" 0402L 7777,4299 r180 bottom value=10.0k
R88 "CRCW040210K0FKED" 0402L 7708,2992 r180 top value=10.0k
R89 "CRCW0402470RJNED" 0402L 7749,3181 r0 top value=470
R90 "CRCW0402470RJNED" 0402L 7748.5,3222.5 r0 top value=470
R91 "CRCW04023K30JNED" 0402L 7841,3217 r180 top value=3.3k
R92 "CRCW040222R0JNED" 0402L 7589,4349 r0 top value=22
R93 "CRCW040222R0JNED" 0402L 7589,4550 r0 top value=22
R94 "CRCW040222R0JNED" 0402L 7589,4599 r0 top value=22
R95 "CRCW040222R0JNED" 0402 4684.37,5385.19 r180 top value=22
R96 "CRCW040222R0JNED" 0402 4684.87,5432.19 r180 top value=22
R97 "CRCW040222R0JNED" 0402 4684.87,5478.69 r180 top value=22
R98 "CRCW040222R0JNED" 0402 4684.87,5526.69 r180 top value=22
R99 "CRCW040222R0JNED" 0402 4673,4197.85 r180 top value=22
R100 "CRCW040222R0JNED" 0402 4673.09,4244.52 r180 top value=22
R101 "CRCW040222R0JNED" 0402 4673.74,4293.01 r180 top value=22
R102 "CRCW040222R0JNED" 0402 4673.3,4339.76 r180 top value=22
R103 "CRCW040222R0JNED" 0402 4689,3124.5 r180 top value=22
R104 "CRCW040222R0JNED" 0402 4689.5,3172.5 r180 top value=22
R105 "CRCW040222R0JNED" 0402 4690,3220.5 r180 top value=22
R106 "CRCW040222R0JNED" 0402 4690.5,3268 r180 top value=22
R107 "CRCW040222R0JNED" 0402L 4667.5,6700.5 r270 top locked value=22
R108 "CRCW040222R0JNED" 0402L 5063.5,6776 r0 top locked value=22
R109 "RC0402JR-070RL" 0402L 4612,6766.5 r90 top locked value=0
R110 "CRCW040222R0JNED" 0402L 4101.5,5628.5 r180 top value=22
R111 "CRCW040222R0JNED" 0402L 4101.5,5725 r180 top value=22
R112 "CRCW040222R0JNED" 0402L 4102,5665.5 r180 top value=22
R113 "CRCW040222R0JNED" 0402 5967,5053 r270 bottom value=22
R114 "CRCW040222R0JNED" 0402 5915,5052.5 r270 bottom value=22
R115 "CRCW040222R0JNED" 0402 5860,5053 r270 bottom value=22
R116 "CRCW040222R0JNED" 0402 5804.5,5052.5 r270 bottom value=22
R117 "CRCW040222R0JNED" 0402 6029,5052.5 r270 bottom value=22
R118 "CRCW040222R0JNED" 0402L 4924.5,4768 r90 top value=22
R119 "CRCW040222R0JNED" 0402L 4997.7,4356.42 r270 top value=22
R120 "CRCW040222R0JNED" 0402L 4895,4358.5 r270 top value=22
R121 "CRCW040222R0JNED" 0402L 4957.5,4357.5 r270 top value=22
R122 "CRCW040222R0JNED" 0402 5598,5053.5 r270 bottom value=22
R123 "CRCW040222R0JNED" 0402 5548.5,5053.5 r270 bottom value=22
R124 "CRCW040222R0JNED" 0402 5430,5051 r270 bottom value=22
R125 "CRCW040222R0JNED" 0402 5363.5,5050.5 r270 bottom value=22
R126 "CRCW040222R0JNED" 0402 5495.5,5052.5 r270 bottom value=22
R127 "CRCW040222R0JNED" 0402 5248.5,5025.5 r0 bottom value=22
R128 "CRCW040222R0JNED" 0402 5248,5074 r0 bottom value=22
R129 "Resistor" 0402 4653,5202.5 r270 bottom value=10k
R130 "Resistor" 0402 4653.5,4048 r270 bottom value=10k
R131 "Resistor" 0402 4673.5,4930.5 r0 bottom value=10k
R132 "Resistor" 0402 4658.5,3766.5 r0 bottom value=10k
R133 "CRCW040222R0JNED" 0402 4195.37,5149.52 r180 bottom value=22
R134 "CRCW040222R0JNED" 0402 4187.5,3985 r180 bottom value=22
R135 "CRCW040222R0JNED" 0402 4195.39,5101.9 r180 bottom value=22
R136 "CRCW040222R0JNED" 0402 4187.5,3937.5 r180 bottom value=22
R137 "CRCW040222R0JNED" 0402 4195.13,5054 r180 bottom value=22
R138 "CRCW040222R0JNED" 0402 4187,3889.5 r180 bottom value=22
R139 "CRCW040222R0JNED" 0402 4195.31,5008.54 r180 bottom value=22
R140 "CRCW040222R0JNED" 0402 4186.5,3842.5 r180 bottom value=22
R141 "CRCW040222R0JNED" 0402 4195.49,4962.35 r180 bottom value=22
R142 "CRCW040222R0JNED" 0402 4186,3795 r180 bottom value=22
R143 "CRCW040222R0JNED" 0402 4194.94,4914.89 r180 bottom value=22
R144 "CRCW040222R0JNED" 0402 4186,3747.5 r180 bottom value=22
R145 "Resistor" 0402 4721.87,5197.31 r0 top value=10k
R146 "Resistor" 0402 4721.37,5149.81 r0 top value=10k
R147 "Resistor" 0402 4721.37,5102.81 r0 top value=10k
R148 "Resistor" 0402 4721.87,5056.81 r0 top value=10k
R149 "Resistor" 0402 4722.87,5009.31 r0 top value=10k
R150 "Resistor" 0402 4723.37,4961.81 r0 top value=10k
R151 "Resistor" 0402 4706.5,4042 r0 top value=10k
R152 "Resistor" 0402 4707,3994 r0 top value=10k
R153 "Resistor" 0402 4707,3947 r0 top value=10k
R154 "Resistor" 0402 4707,3899.5 r0 top value=10k
R155 "Resistor" 0402 4707,3852 r0 top value=10k
R156 "Resistor" 0402 4707,3803.5 r0 top value=10k
R157 "Resistor" 0402 4655.5,4802 r270 bottom value=10k
R158 "Resistor" 0402 4689.68,3642.19 r270 bottom value=10k
R159 "Resistor" 0402 4661,4528.5 r0 bottom value=10k
R160 "Resistor" 0402 4667,3360 r0 bottom value=10k
R161 "CRCW040222R0JNED" 0402 4191.96,4743.98 r180 bottom value=22
R162 "CRCW040222R0JNED" 0402 4192.5,3578.5 r180 bottom value=22
R163 "CRCW040222R0JNED" 0402 4191.96,4696.98 r180 bottom value=22
R164 "CRCW040222R0JNED" 0402 4192.5,3531 r180 bottom value=22
R165 "CRCW040222R0JNED" 0402 4192.01,4649.73 r180 bottom value=22
R166 "CRCW040222R0JNED" 0402 4192.5,3483 r180 bottom value=22
R167 "CRCW040222R0JNED" 0402 4191.77,4602.68 r180 bottom value=22
R168 "CRCW040222R0JNED" 0402 4192.5,3435 r180 bottom value=22
R169 "CRCW040222R0JNED" 0402 4192.25,4556.31 r180 bottom value=22
R170 "CRCW040222R0JNED" 0402 4192.5,3387.5 r180 bottom value=22
R171 "CRCW040222R0JNED" 0402 4192.69,4510.4 r180 bottom value=22
R172 "CRCW040222R0JNED" 0402 4192,3339.5 r180 bottom value=22
R173 "Resistor" 0402 4699,4800 r0 top value=10k
R174 "Resistor" 0402 4699,4752 r0 top value=10k
R175 "Resistor" 0402 4698.5,4704.5 r0 top value=10k
R176 "Resistor" 0402 4699,4659.5 r0 top value=10k
R177 "Resistor" 0402 4699,4612 r0 top value=10k
R178 "Resistor" 0402 4699,4564.5 r0 top value=10k
R179 "Resistor" 0402 4707,3630.38 r0 top value=10k
R180 "Resistor" 0402 4706.75,3582.96 r0 top value=10k
R181 "Resistor" 0402 4706.75,3536.53 r0 top value=10k
R182 "Resistor" 0402 4706.14,3488.88 r0 top value=10k
R183 "Resistor" 0402 4706.6,3441.14 r0 top value=10k
R184 "Resistor" 0402 4706.5,3394 r0 top value=10k
R185 "Resistor" 0402 4650,2974.5 r270 bottom value=10k
R186 "Resistor" 0402 4665.5,2702 r0 bottom value=10k
R187 "CRCW040222R0JNED" 0402 4189.84,2919.67 r180 bottom value=22
R188 "CRCW040222R0JNED" 0402 4190,2871.5 r180 bottom value=22
R189 "CRCW040222R0JNED" 0402 4190,2823.5 r180 bottom value=22
R190 "CRCW040222R0JNED" 0402 4190,2775.5 r180 bottom value=22
R191 "CRCW040222R0JNED" 0402 4190,2727 r180 bottom value=22
R192 "CRCW040222R0JNED" 0402 4190.5,2679.5 r180 bottom value=22
R193 "Resistor" 0402 4712,2973 r0 top value=10k
R194 "Resistor" 0402 4712,2925.5 r0 top value=10k
R195 "Resistor" 0402 4712,2878 r0 top value=10k
R196 "Resistor" 0402 4712,2830.5 r0 top value=10k
R197 "Resistor" 0402 4712,2783 r0 top value=10k
R198 "Resistor" 0402 4712,2735.5 r0 top value=10k
R199 "Resistor" 0402 4667.98,2604.52 r270 bottom value=10k
R200 "Resistor" 0402 4663,2300 r0 bottom value=10k
R201 "CRCW040222R0JNED" 0402 4189.5,2518.5 r180 bottom value=22
R202 "CRCW040222R0JNED" 0402 4189.5,2470.5 r180 bottom value=22
R203 "CRCW040222R0JNED" 0402 4189,2423 r180 bottom value=22
R204 "CRCW040222R0JNED" 0402 4189,2374.5 r180 bottom value=22
R205 "CRCW040222R0JNED" 0402 4189,2326.5 r180 bottom value=22
R206 "CRCW040222R0JNED" 0402 4188.5,2278.5 r180 bottom value=22
R207 "Resistor" 0402 4706.6,2568.14 r0 top value=10k
R208 "Resistor" 0402 4707.27,2520.93 r0 top value=10k
R209 "Resistor" 0402 4706.86,2474.24 r0 top value=10k
R210 "Resistor" 0402 4707.48,2427.13 r0 top value=10k
R211 "Resistor" 0402 4707.05,2379.44 r0 top value=10k
R212 "Resistor" 0402 4707.23,2331.56 r0 top value=10k
R213 "CRCW04022K49FKED" 0402 6786.66,6140.61 r270 bottom value=2.49k
R214 "CRCW04022K49FKED" 0402 6834.79,6140.56 r270 bottom value=2.49k
R215 "CRCW04022K49FKED" 0402 7022.5,6368.5 r0 top locked value=2.49k
R216 "CRCW04022K49FKED" 0402 6991.01,6560.55 r0 bottom value=2.49k
R217 "CRCW04022K49FKED" 0402 6991.12,6513.53 r0 bottom value=2.49k
R218 "CRCW04022K49FKED" 0402 6958.33,6464.94 r0 bottom value=2.49k
R219 "CRCW04022K49FKED" 0402 6526,6406.5 r90 bottom value=2.49k
R220 "CRCW040222R0JNED" 0402 6185,3427 r0 bottom value=22
R221 "CRCW04022K49FKED" 0402 6782,6139.5 r90 top value=2.49k
R222 "CRCW04022K49FKED" 0402 6825,6139.5 r90 top value=2.49k
R223 "CRCW04022K49FKED" 0402 6998.11,6369.26 r180 bottom value=2.49k
R224 "CRCW04022K49FKED" 0402 6993,6633.5 r180 top locked value=2.49k
R225 "CRCW04022K49FKED" 0402 6992.5,6585.5 r180 top locked value=2.49k
R226 "CRCW04022K49FKED" 0402 6993.7,6535.58 r180 top value=2.49k
R227 "CRCW04022K49FKED" 0402 6502,6330.5 r0 bottom value=2.49k
R228 "CRCW040222R0JNED" 0402L 6920.5,6259 r270 bottom value=22
R229 "CRCW080575R0FKEA" 0805_HV 6443,7601.5 r270 bottom value=75.0
R230 "CRCW040222R0JNED" 0402L 6762.5,6270.5 r90 top value=22
R231 "CRCW080575R0FKEA" 0805_HV 6592.5,7601 r270 bottom value=75.0
R232 "CRCW0402200RFKED" 0402 6250,7043 r0 top value=200
R233 "CRCW040222R0JNED" 0402L 6798.98,6258.75 r90 top value=22
R234 "CRCW040222R0JNED" 0402L 6835,6258.5 r90 top value=22
R235 "CRCW040211K0FKED" 0402 6580,6655 r180 top locked value=11.0k
R236 "CRCW04022K20JNED" 0402 6442,5088.5 r90 bottom value=2.2k
R237 "CRCW040222R0JNED" 0402L 6871,6259 r90 top value=22
R238 "CRCW040222R0JNED" 0402L 6906.72,6259 r90 top value=22
R239 "CRCW0402200RFKED" 0402 7102.5,7070 r90 top value=200
R240 "CRCW04021K00JNED" 0402 6343,6913.5 r270 top value=1.0k
R241 "ERJ-2GE0R00X" 0402L 4636,5293 r0 top value=0
R242 "CRCW04022K20FKED" 0402L 6971.66,6494.19 r180 top value=2.20k
R243 "CRCW04022K20FKED" 0402L 6971.19,6453.13 r180 top value=2.20k
R244 "CRCW04021K00JNED" 0402 7181.5,6903 r90 top value=1.0k
R245 "CRCW080575R0FKEA" 0805_HV 6743.5,7600.5 r270 bottom value=75.0
R246 "CRCW04020000Z0ED" 0402 6484,6394.5 r0 top locked value=0
R247 "CRCW040222R0JNED" 0402L 5792,6259 r270 bottom value=22
R248 "CRCW080575R0FKEA" 0805_HV 6892.5,7601 r270 bottom value=75.0
R249 "CRCW20101M00JNEF" 2010 7297,7831 r270 bottom value=1.0Meg
R250 "CRCW04021K00JNED" 0402 7105.5,6908 r90 top value=1.0k
R251 "CRCW04021K00JNED" 0402 6292.5,6913.5 r90 top value=1.0k
R252 "CRCW20101M00JNEF" 2010 6106,7626 r90 bottom value=1.0Meg
R253 "CRCW040210K0FKED" 0402 5658.5,6138 r270 bottom value=10.0k
R254 "CRCW04022K49FKED" 0402 5702,6138 r270 bottom value=2.49k
R255 "CRCW04022K49FKED" 0402 5897,6370 r0 top locked value=2.49k
R256 "CRCW04022K49FKED" 0402 5868,6560 r0 bottom value=2.49k
R257 "CRCW04022K49FKED" 0402 5868,6515 r0 bottom value=2.49k
R258 "CRCW04022K49FKED" 0402 5836,6467 r0 bottom value=2.49k
R259 "CRCW04022K49FKED" 0402 5393,6403 r90 bottom value=2.49k
R260 "CRCW04020000Z0ED" 0402 5357.5,6349 r0 top locked value=0
R261 "CRCW04022K49FKED" 0402 5656.5,6139 r90 top locked value=2.49k
R262 "CRCW04022K49FKED" 0402 5700.5,6139.5 r90 top locked value=2.49k
R263 "CRCW04022K49FKED" 0402 5873.13,6370.25 r180 bottom value=2.49k
R264 "CRCW04022K49FKED" 0402 5868.5,6632.5 r180 top locked value=2.49k
R265 "CRCW04022K49FKED" 0402 5868,6585.5 r180 top locked value=2.49k
R266 "CRCW04022K49FKED" 0402 5868.5,6532 r180 top locked value=2.49k
R267 "CRCW04022K49FKED" 0402 5366,6326 r0 bottom value=2.49k
R268 "ERJ-2GE0R00X" 0402L 4270,5289.5 r180 top value=0
R269 "CRCW080575R0FKEA" 0805_HV 5318,7603 r270 bottom value=75.0
R270 "CRCW040222R0JNED" 0402L 5637.5,6271.5 r90 top value=22
R271 "CRCW080575R0FKEA" 0805_HV 5468,7603 r270 bottom value=75.0
R272 "CRCW0402200RFKED" 0402 5115,7045.5 r0 top locked value=200
R273 "CRCW040222R0JNED" 0402L 5673,6258 r90 top value=22
R274 "CRCW040222R0JNED" 0402L 5709.5,6258.5 r90 top value=22
R275 "CRCW040211K0FKED" 0402 5457,6690 r90 top locked value=11.0k
R276 "ERJ-2GE0R00X" 0402L 4640,4110.5 r0 top value=0
R277 "CRCW040222R0JNED" 0402L 5746.5,6258.5 r90 top value=22
R278 "CRCW040222R0JNED" 0402L 5785.31,6258.28 r90 top value=22
R279 "CRCW0402200RFKED" 0402 5971,7063 r90 top locked value=200
R280 "CRCW04021K00JNED" 0402 5209,6917.5 r270 top locked value=1.0k
R281 "ERJ-2GE0R00X" 0402L 4263,4111 r180 top value=0
R282 "CRCW04022K20FKED" 0402L 5850.77,6492.12 r180 top value=2.20k
R283 "CRCW04022K20FKED" 0402L 5848.34,6455.19 r180 top value=2.20k
R284 "CRCW04021K00JNED" 0402 6054.88,6856 r180 top locked value=1.0k
R285 "CRCW080575R0FKEA" 0805_HV 5619,7602 r270 bottom value=75.0
R286 "CRCW04020000Z0ED" 0402 5358.5,6394.5 r0 top locked value=0
R287 "CRCW080575R0FKEA" 0805_HV 5766,7603 r270 bottom value=75.0
R288 "CRCW20101M00JNEF" 2010 5050,7830 r270 bottom value=1.0Meg
R289 "CRCW04021K00JNED" 0402 5964.5,6905.5 r90 top locked value=1.0k
R290 "CRCW04021K00JNED" 0402 5153,6915.5 r90 top locked value=1.0k
R291 "ERJ-2GE0R00X" 0402L 4636.5,3037.5 r0 top value=0
R292 "CRCW040210K0FKED" 0402L 4255.5,1905.5 r270 top value=10.0k
R293 "CRCW040222R0JNED" 0402 4222.5,1770 r180 top value=22
R294 "CRCW040222R0JNED" 0402 4222.5,1818 r180 top value=22
R295 "CRCW040222R0JNED" 0402 4681.5,1843.5 r180 top value=22
R296 "CRCW040210K0FKED" 0402L 4184.65,6283.46 r0 top value=10.0k
R297 "CRCW040210K0FKED" 0402L 4185.5,6318.5 r0 top value=10.0k
R298 "CRCW040210K0FKED" 0402L 4186,6354 r0 top value=10.0k
R299 "CRCW040210K0FKED" 0402L 4186,6389 r0 top value=10.0k
R300 "CRCW040210K0FKED" 0402L 4362,6624 r90 top value=10.0k
R301 "CRCW040222R0JNED" 0402 4198,2043.5 r180 top value=22
R302 "CRCW040222R0JNED" 0402 4198,2091.5 r180 top value=22
R303 "CRCW040222R0JNED" 0402 4198.5,2139 r180 top value=22
R304 "CRCW040222R0JNED" 0402 6817.5,3785 r180 bottom value=22
R305 "CRCW04020000Z0ED" 0402 6483.5,6349.5 r0 top locked value=0
R306 "ERJ-2GE0R00X" 0402L 6798.5,4886.5 r180 bottom value=0
R307 "ERJ-2GE0R00X" 0402L 6798.5,4844 r180 bottom value=0
R308 "CRCW0402200RFKED" 0402 6817,3707 r180 bottom value=200
R309 "ERJ-2GE0R00X" 0402L 6494.5,3433 r270 bottom value=0
R310 "ERJ-2GE0R00X" 0402L 6455.5,3436.5 r270 bottom value=0
R311 "RT0603DRE0749K9L" 0603 7169.86,1202.91 r270 top locked value=49.9k
R312 "RT0603DRE0749K9L" 0603 7355.17,1206.19 r270 top locked value=49.9k
R313 "RT0603DRE0749K9L" 0603 7544.62,1209.74 r270 top locked value=49.9k
R314 "RT0603DRE073K4L" 0603 7137.86,1299.9 r0 top locked value=3.40k
R315 "RT0603DRE073K4L" 0603 7322.5,1302.5 r0 top locked value=3.40k
R316 "RT0603DRE073K4L" 0603 7511.88,1304.55 r0 top locked value=3.40k
R317 "ERJ-2GE0R00X" 0402L 4264.5,3037 r180 top value=0
R318 "ERJ-2GE0R00X" 0402L 4468.5,5777.5 r180 top value=0
R319 "ERJ-2GE0R00X" 0402L 4640,5721 r90 top value=0
R320 "ERJ-2GE0R00X" 0402L 4596.65,4119.92 r0 bottom value=0
R321 "ERJ-2GE0R00X" 0402L 4262.5,4071.5 r180 bottom value=0
R322 "ERJ-2GE0R00X" 0402L 4593.45,5282.03 r0 bottom value=0
R323 "ERJ-2GE0R00X" 0402L 4266.5,5237.5 r180 bottom value=0
R324 "ERJ-2GE0R00X" 0402L 4624.5,3688 r90 bottom value=0
R325 "ERJ-2GE0R00X" 0402L 4266,3666 r180 bottom value=0
R326 "ERJ-2GE0R00X" 0402L 4640.5,4870.5 r0 bottom value=0
R327 "ERJ-2GE0R00X" 0402L 4265,4830 r180 bottom value=0
R328 "ERJ-2GE0R00X" 0402L 4590.67,3047.9 r0 bottom value=0
R329 "ERJ-2GE0R00X" 0402L 4260.5,3003 r180 bottom value=0
R330 "ERJ-2GE0R00X" 0402L 4625.19,2623.37 r90 bottom value=0
R331 "ERJ-2GE0R00X" 0402L 4268.5,2602.5 r180 bottom value=0
R332 "ERJ-2GE0R00X" 0402L 4635,1665.5 r0 top value=0
R333 "ERJ-2GE0R00X" 0402L 4260.5,1667 r180 top value=0
R334 "ERJ-2GE0R00X" 0402L 4637.5,6170.5 r0 top locked value=0
R335 "ERJ-2GE0R00X" 0402L 4266.5,6172 r180 top value=0
R336 "ERJ-2GE0R00X" 0402L 4636.5,1361.5 r0 top value=0
R337 "ERJ-2GE0R00X" 0402L 4263.5,1361 r180 top value=0
R338 "ERJ-2GE0R00X" 0402L 4350.65,6524.08 r180 top value=0
R339 "ERJ-2GE0R00X" 0402L 4637,5831 r0 top locked value=0
R340 "ERJ-2GE0R00X" 0402L 4272,5832.3 r180 top value=0
R341 "ERJ-2GE0R00X" 0402L 4639,1970.5 r0 top value=0
R342 "ERJ-2GE0R00X" 0402L 4250.5,1998 r180 top value=0
R343 "ERJ-2GE0R00X" 0402L 4591,6621 r90 top locked value=0
S1 "434121025816" SW_434121025816 7284,4002 r180 top
SW1 "418121270804" FP-418121270804_SMT_SW_11MM1_6MM2-MFG 6944,2595 r0 top locked
SW2 "418121270804" FP-418121270804_SMT_SW_11MM1_6MM2-MFG 5940,2595 r0 top locked
SW3 "418121270804" FP-418121270804_SMT_SW_11MM1_6MM2-MFG 6444,2595 r0 top locked
SW4 "418121270804" FP-418121270804_SMT_SW_11MM1_6MM2-MFG 5437,2595 r0 top locked
T1 "749020011A" FP-749020011A_SMT_17MM5_14MM2-MFG 6717,7355 r0 top locked
T2 "749020011A" FP-749020011A_SMT_17MM5_14MM2-MFG 5592,7355 r0 top locked
TP1 "5129" Keystone5129 7645,7077 r0 top
TP2 "5129" Keystone5129 2165,8204 r0 top
TP3 "5129" Keystone5129 2165,5006.5 r0 top
TP4 "5129" Keystone5129 1477,2304.5 r0 top
TP5 "5129" Keystone5129 5416,1209.5 r0 top locked
TP6 "5129" Keystone5129 7367.5,6653.5 r0 top
TP7 "5129" Keystone5129 7363.5,6292.5 r0 top
TP8 "5129" Keystone5129 6299.5,1625 r0 top
TP9 "5129" Keystone5129 5666,816 r0 top locked
TP10 "TESTPOINT" TP_25MIL-SMT 6684.86,6253.03 r90 top locked
TP11 "TESTPOINT" TP_25MIL-SMT 6973.29,6303.66 r90 top
TP12 "TESTPOINT" TP_25MIL-SMT 6742.36,6185.53 r90 top
TP13 "TESTPOINT" TP_25MIL-SMT 5240,6321.5 r90 top locked
TP14 "TESTPOINT" TP_25MIL-SMT 6949.74,6409.91 r90 top
TP15 "TESTPOINT" TP_25MIL-SMT 5560,6253.5 r90 top locked
TP16 "TESTPOINT" TP_25MIL-SMT 5835,6318 r90 top locked
TP17 "TESTPOINT" TP_25MIL-SMT 5826,6370.5 r90 top locked
TP18 "TESTPOINT" TP_25MIL-SMT 5617.5,6186 r90 top locked
TP19 "TESTPOINT" TP_25MIL-SMT 5825,6410.5 r90 top locked
TP20 "TESTPOINT" TP_25MIL-SMT 5441,3213 r90 top
TP21 "TESTPOINT" TP_25MIL-SMT 6382.5,6336 r90 top
TP22 "TESTPOINT" TP_25MIL-SMT 5774,1544 r90 top locked
TP23 "TESTPOINT" TP_25MIL-SMT 4489,5643.58 r90 top
TP24 "TESTPOINT" TP_25MIL-SMT 4489,5695.8 r90 top
TP25 "TESTPOINT" TP_25MIL-SMT 4882.5,4788.5 r90 top
TP26 "TESTPOINT" TP_25MIL-SMT 5042,4336.5 r90 top
TP27 "TESTPOINT" TP_25MIL-SMT 4897,4270.5 r90 top
TP28 "TESTPOINT" TP_25MIL-SMT 4978,4750.24 r90 top
TP29 "TESTPOINT" TP_25MIL-SMT 4957.5,4270 r90 top
TP30 "TESTPOINT" TP_25MIL-SMT 4672.78,5643.88 r90 top
TP31 "TESTPOINT" TP_25MIL-SMT 6916.5,6605.5 r90 top locked
TP32 "TESTPOINT" TP_25MIL-SMT 7017.88,6417.85 r90 top
TP33 "TESTPOINT" TP_25MIL-SMT 6949.44,6363.32 r90 top
TP34 "5129" Keystone5129 6419,819 r0 top locked
TP35 "TESTPOINT" TP_25MIL-SMT 5791.5,6606.5 r90 top locked
TP36 "TESTPOINT" TP_25MIL-SMT 5896,6428.86 r90 top
TP37 "TESTPOINT" TP_25MIL-SMT 4739,1727.5 r90 top
TP38 "TESTPOINT" TP_25MIL-SMT 4686,1801 r90 top
TP39 "TESTPOINT" TP_25MIL-SMT 4746.25,1882.75 r90 top
TP40 "5129" Keystone5129 7842,2629 r0 top
TP41 "5129" Keystone5129 7825.5,808 r0 top
U1 "TLVM13660RDLR" RDL0020A-MFG 6003.47,819.42 r270 top locked
U2 "LM74502HDDF" DDF0008A-MFG 6923,825 r0 top locked
U3 "TPS62827DMQT" DMQ0006A 5684,1486 r270 top locked
U4 "TPSM82822SILR" SIL0010D 7684.6,6627.26 r180 top locked
U5 "TPSM82822SILR" SIL0010D 7688.61,6261.05 r180 top locked
U6 "TPS62827DMQT" DMQ0006A 6037,1344 r90 top locked
U7 "TMUX1574RSVR" RSV0016A 6947,2608 r270 bottom locked
U8 "TMUX1574RSVR" RSV0016A 6447,2608 r270 bottom locked
U9 "TMUX1574RSVR" RSV0016A 5941,2608 r270 bottom locked
U10 "TMUX1574RSVR" RSV0016A 5440,2608 r270 bottom locked
U11 "SN74AHC1G125DBVR" DBV0005A_N 5322,3088 r180 top
U12 "FT232RQ-REEL" QFN32-5x5MM 7572.46,5288.84 r270 bottom locked
U13 "ISO7721D" D0008B_HV 6871,5418 r0 top locked
U14 "TLV70733DQNT" DQN0004A 7633.06,5843.2 r180 top
U15 "TPD4S009DBVR" DBV0006A_L 7512,3553 r270 bottom
U16 "TPD4S009DBVR" DBV0006A_L 7513,3352 r270 bottom
U17 "TPS22963CYZPR" YZP0006AFAF 7749,3090 r270 top
U18 "SN74AXC4T245PWT" PW0016A_N 4455.3,5431 r180 top
U19 "SN74AXC4T245PWT" PW0016A_N 4450,4245.5 r180 top
U20 "SN74AXC4T245PWT" PW0016A_N 4450,3170 r180 top
U21 "SN74AXC2T245RSW" RSW0010A 4582.64,5628.13 r90 top
U22 "LMK1C1102PWR" PW0008A-MFG 4866.5,6738 r0 top locked
U23 "LMK1C1104PWR" PW0008A-MFG 4293,5681.5 r180 top locked
U24 "LMK1C1104PWR" PW0008A-MFG 4938,4547 r270 top
U25 "SN74AXC8T245PWR" PW0024A_N 4453,5047 r180 bottom
U26 "SN74AXC8T245PWR" PW0024A_N 4449,3882 r180 bottom
U27 "SN74AXC8T245PWR" PW0024A_N 4453,4641.09 r180 bottom
U28 "SN74AXC8T245PWR" PW0024A_N 4453,3475 r180 bottom
U29 "SN74AXC8T245PWR" PW0024A_N 4453,2816.5 r180 bottom locked
U30 "SN74AXC8T245PWR" PW0024A_N 4453,2415 r180 bottom locked
U31 "DP83869HMRGZT" RGZ0048B-MFG 6730,6459 r270 top locked
U32 "TPD2E2U06DRLR" DRL0005A 6965.5,6930 r90 top locked
U33 "TPD2E2U06DRLR" DRL0005A 6815.5,6930.5 r90 top locked
U34 "TPD2E2U06DRLR" DRL0005A 6666.5,6930.5 r90 top locked
U35 "TPD2E2U06DRLR" DRL0005A 6514.5,6930.5 r90 top locked
U36 "DP83869HMRGZT" RGZ0048B-MFG 5605.14,6459.47 r270 top locked
U37 "TPD2E2U06DRLR" DRL0005A 5842,6931 r90 top locked
U38 "TPD2E2U06DRLR" DRL0005A 5692,6930 r90 top locked
U39 "TPD2E2U06DRLR" DRL0005A 5541,6930 r90 top locked
U40 "TPD2E2U06DRLR" DRL0005A 5391,6932 r90 top locked
U41 "SN74AXC4T245PWT" PW0016A_N 4450,1804.5 r180 top
U42 "SN74AXC4T245PWT" PW0016A_N 4453,6308.5 r180 top
U43 "SN74AXC4T245PWT" PW0016A_N 4453,1500 r180 top
U44 "SN74AXC4T245PWT" PW0016A_N 4455,5970 r180 top
U45 "SN74AXC4T245PWT" PW0016A_N 4452,2106.5 r180 top
U46 "2N7001TDCKR" DCK0005A_N 4453,6590 r180 top
Y1 "PLMK6CE02500CDLFT" DLF0004A-MFG 4642.5,6886.5 r0 top locked

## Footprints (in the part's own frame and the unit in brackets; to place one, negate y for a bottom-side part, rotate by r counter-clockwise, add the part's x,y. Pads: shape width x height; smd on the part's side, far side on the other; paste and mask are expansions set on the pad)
0201 [mm] "Data from Kemet datasheet CC101_COM dated 7/28/11"
  rect 0.46x0.42 smd mask+0.048: 1(-0.33,0) 2(0.33,0)
  body extent -0.31,-0.16 0.31,0.16, height 0.26
0201_033 [mm] "SMD, 2-Leads, Height 0.33mm"
  rect 0.46x0.42 smd mask+0.048: 1(-0.33,0) 2(0.33,0)
  body extent -0.31,-0.16 0.31,0.16, height 0.33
